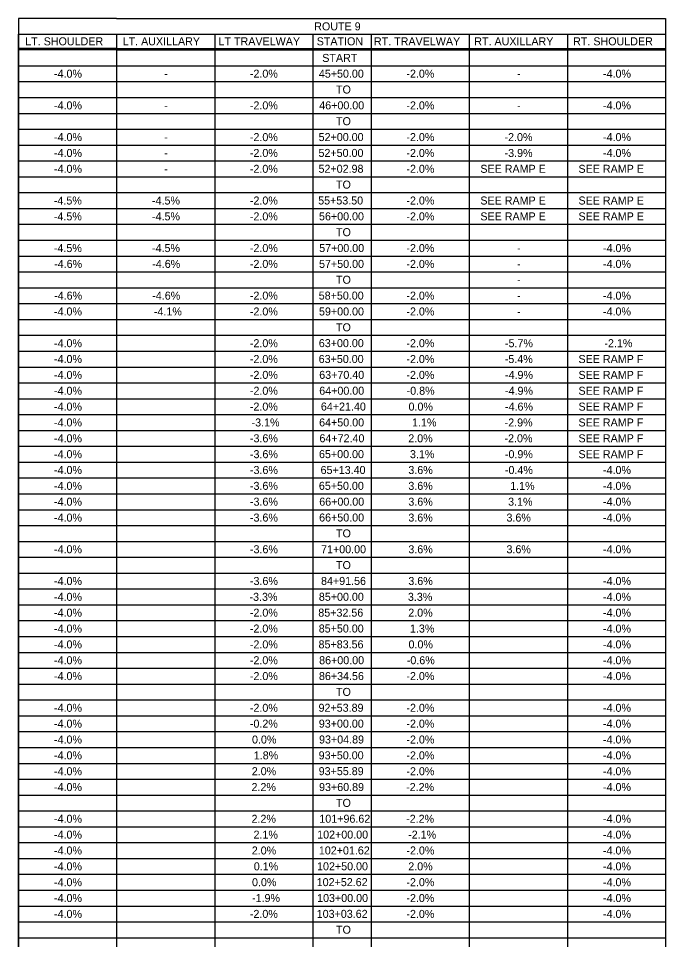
# Model space of a CAD drawing. Extents: x -15319374 to 1762012, y 465773 to 3693661.
# Drawn here: x -15318877.5 to -15318635, y 3691629.9 to 3691975.2 of the extents above; entities that cross this region are included whole.
import ezdxf

# ---------------------------------------------------------------- set-up
doc = ezdxf.new("R2010")
doc.units = 0
doc.layers.add('BORDER', color=7, linetype='Continuous')
doc.layers.add('DIMENSIONS', color=7, linetype='Continuous')

msp = doc.modelspace()

# ---------------------------------------------------------------- linework, layer by layer
at = {"layer": 'BORDER'}
for p, q in [((-15318877.49, 3691969.22), (-15318877.49, 3691464.16)), ((-15318840.73, 3691969.22), (-15318840.73, 3691285.88)), ((-15318803.96, 3691969.22), (-15318803.96, 3691285.88)), ((-15318767.19, 3691969.22), (-15318767.19, 3691285.88)), ((-15318745.32, 3691969.22), (-15318745.32, 3691285.88)), ((-15318708.55, 3691969.22), (-15318708.55, 3691285.88)), ((-15318671.78, 3691969.22), (-15318671.78, 3691285.88)), ((-15318635.01, 3691969.22), (-15318635.01, 3691464.16)), ((-15318840.73, 3691963.94), (-15318877.49, 3691963.94)), ((-15318840.73, 3691963.35), (-15318877.49, 3691963.35)), ((-15318877.49, 3691963.35), (-15318877.49, 3691285.88)), ((-15318840.73, 3691963.94), (-15318635.01, 3691963.94)), ((-15318840.73, 3691963.35), (-15318635.01, 3691963.35)), ((-15318877.49, 3691957.4), (-15318635.01, 3691957.4)), ((-15318877.49, 3691957.4), (-15318635.01, 3691957.4)), ((-15318877.49, 3691957.4), (-15318635.01, 3691957.4)), ((-15318877.49, 3691951.46), (-15318635.01, 3691951.46)), ((-15318877.49, 3691945.52), (-15318635.01, 3691945.52)), ((-15318877.49, 3691939.58), (-15318635.01, 3691939.58)), ((-15318877.49, 3691933.63), (-15318635.01, 3691933.63)), ((-15318877.49, 3691927.69), (-15318635.01, 3691927.69)), ((-15318877.49, 3691921.75), (-15318635.01, 3691921.75)), ((-15318877.49, 3691915.8), (-15318635.01, 3691915.8)), ((-15318877.49, 3691909.86), (-15318635.01, 3691909.86)), ((-15318877.49, 3691903.92), (-15318635.01, 3691903.92)), ((-15318877.49, 3691897.98), (-15318635.01, 3691897.98)), ((-15318877.49, 3691892.03), (-15318635.01, 3691892.03)), ((-15318877.49, 3691886.09), (-15318635.01, 3691886.09)), ((-15318877.49, 3691880.15), (-15318635.01, 3691880.15)), ((-15318877.49, 3691874.21), (-15318635.01, 3691874.21)), ((-15318877.49, 3691868.26), (-15318635.01, 3691868.26)), ((-15318877.49, 3691862.32), (-15318635.01, 3691862.32)), ((-15318877.49, 3691856.38), (-15318635.01, 3691856.38)), ((-15318877.49, 3691850.43), (-15318635.01, 3691850.43)), ((-15318877.49, 3691844.49), (-15318635.01, 3691844.49)), ((-15318877.49, 3691838.55), (-15318635.01, 3691838.55)), ((-15318877.49, 3691832.61), (-15318635.01, 3691832.61)), ((-15318877.49, 3691826.66), (-15318635.01, 3691826.66)), ((-15318877.49, 3691820.72), (-15318635.01, 3691820.72)), ((-15318877.49, 3691814.78), (-15318635.01, 3691814.78)), ((-15318877.49, 3691808.84), (-15318635.01, 3691808.84)), ((-15318877.49, 3691802.89), (-15318635.01, 3691802.89)), ((-15318877.49, 3691796.95), (-15318635.01, 3691796.95)), ((-15318877.49, 3691791.01), (-15318635.01, 3691791.01)), ((-15318877.49, 3691785.07), (-15318635.01, 3691785.07)), ((-15318877.49, 3691779.12), (-15318635.01, 3691779.12)), ((-15318877.49, 3691773.18), (-15318635.01, 3691773.18)), ((-15318877.49, 3691767.24), (-15318635.01, 3691767.24)), ((-15318877.49, 3691761.29), (-15318635.01, 3691761.29)), ((-15318877.49, 3691755.35), (-15318635.01, 3691755.35)), ((-15318877.49, 3691749.41), (-15318635.01, 3691749.41)), ((-15318877.49, 3691743.47), (-15318635.01, 3691743.47)), ((-15318877.49, 3691737.52), (-15318635.01, 3691737.52)), ((-15318877.49, 3691731.58), (-15318635.01, 3691731.58)), ((-15318877.49, 3691725.64), (-15318635.01, 3691725.64)), ((-15318877.49, 3691719.7), (-15318635.01, 3691719.7)), ((-15318877.49, 3691713.75), (-15318635.01, 3691713.75)), ((-15318877.49, 3691707.81), (-15318635.01, 3691707.81)), ((-15318877.49, 3691701.87), (-15318635.01, 3691701.87)), ((-15318877.49, 3691695.92), (-15318635.01, 3691695.92)), ((-15318877.49, 3691689.98), (-15318635.01, 3691689.98)), ((-15318877.49, 3691684.04), (-15318635.01, 3691684.04)), ((-15318877.49, 3691678.1), (-15318635.01, 3691678.1)), ((-15318877.49, 3691672.15), (-15318635.01, 3691672.15)), ((-15318877.49, 3691666.21), (-15318635.01, 3691666.21)), ((-15318877.49, 3691660.27), (-15318635.01, 3691660.27)), ((-15318877.49, 3691654.33), (-15318635.01, 3691654.33)), ((-15318877.49, 3691648.38), (-15318635.01, 3691648.38)), ((-15318877.49, 3691642.44), (-15318635.01, 3691642.44)), ((-15318877.49, 3691636.5), (-15318635.01, 3691636.5)), ((-15318877.49, 3691630.55), (-15318635.01, 3691630.55))]:
    msp.add_line(p, q, dxfattribs=at)
for points in [[(-15318840.73, 3691975.17), (-15318877.49, 3691975.17), (-15318877.49, 3691969.22)], [(-15318840.73, 3691975.17), (-15318671.78, 3691975.17)], [(-15318671.78, 3691975.17), (-15318635.01, 3691975.17), (-15318635.01, 3691969.22)]]:
    msp.add_lwpolyline(points, dxfattribs=at)
msp.add_lwpolyline([(-15318877.49, 3691969.22), (-15318635.01, 3691969.22), (-15318635.01, 3691624.61), (-15318877.49, 3691624.61)], close=True, dxfattribs=at)

# ---------------------------------------------------------------- texts
at = {"layer": 'DIMENSIONS'}
for s, p in [('ROUTE 9', (-15318766.66, 3691970.69)), ('LT. SHOULDER', (-15318874.94, 3691965.08)), ('LT. AUXILLARY', (-15318838.44, 3691965.08)), ('LT TRAVELWAY', (-15318802.51, 3691965.08)), ('STATION', (-15318765.73, 3691965.08)), ('RT. TRAVELWAY', (-15318744.29, 3691965.08)), ('RT. AUXILLARY', (-15318706.69, 3691965.08)), ('RT. SHOULDER', (-15318669.65, 3691965.08)), ('START', (-15318763.65, 3691958.86)), ('-4.0%', (-15318864.16, 3691952.95)), ('-', (-15318822.85, 3691952.95)), ('-2.0%', (-15318790.77, 3691952.95)), ('45+50.00', (-15318764.92, 3691952.96)), ('-2.0%', (-15318732.12, 3691952.95)), ('-', (-15318690.67, 3691952.95)), ('-4.0%', (-15318658.45, 3691952.95)), ('TO', (-15318758.49, 3691947.02)), ('-4.0%', (-15318864.16, 3691941.06)), ('-2.0%', (-15318790.77, 3691941.06)), ('46+00.00', (-15318764.78, 3691941.08)), ('-2.0%', (-15318732.12, 3691941.06)), ('-4.0%', (-15318658.45, 3691941.06)), ('-', (-15318822.85, 3691941.06)), ('-', (-15318690.67, 3691941.06)), ('TO', (-15318758.49, 3691935.14)), ('-4.0%', (-15318864.16, 3691929.18)), ('-2.0%', (-15318790.77, 3691929.18)), ('52+00.00', (-15318765.01, 3691929.19)), ('-2.0%', (-15318732.12, 3691929.18)), ('-2.0%', (-15318695.36, 3691929.18)), ('-4.0%', (-15318658.45, 3691929.18)), ('-', (-15318822.85, 3691929.18)), ('-4.0%', (-15318864.16, 3691923.23)), ('-2.0%', (-15318790.77, 3691923.23)), ('52+50.00', (-15318765.06, 3691923.25)), ('-2.0%', (-15318732.12, 3691923.23)), ('-3.9%', (-15318695.33, 3691923.23)), ('-4.0%', (-15318658.45, 3691923.23)), ('-', (-15318822.85, 3691923.23)), ('-4.0%', (-15318864.16, 3691917.29)), ('-', (-15318822.85, 3691917.29)), ('-2.0%', (-15318790.77, 3691917.29)), ('52+02.98', (-15318765.05, 3691917.31)), ('-2.0%', (-15318732.12, 3691917.29)), ('SEE RAMP E', (-15318704.41, 3691917.29)), ('SEE RAMP E', (-15318667.64, 3691917.29)), ('TO', (-15318758.49, 3691911.37)), ('-4.5%', (-15318864.21, 3691905.41)), ('-4.5%', (-15318827.44, 3691905.41)), ('-2.0%', (-15318790.77, 3691905.41)), ('55+53.50', (-15318765.18, 3691905.42)), ('-2.0%', (-15318732.12, 3691905.41)), ('SEE RAMP E', (-15318704.41, 3691905.41)), ('SEE RAMP E', (-15318667.64, 3691905.41)), ('-4.5%', (-15318864.21, 3691899.46)), ('-4.5%', (-15318827.44, 3691899.46)), ('-2.0%', (-15318790.77, 3691899.46)), ('56+00.00', (-15318764.87, 3691899.48)), ('-2.0%', (-15318732.12, 3691899.46)), ('SEE RAMP E', (-15318704.41, 3691899.46)), ('SEE RAMP E', (-15318667.64, 3691899.46)), ('TO', (-15318758.49, 3691893.54)), ('-4.5%', (-15318864.21, 3691887.58)), ('-4.5%', (-15318827.44, 3691887.58)), ('-2.0%', (-15318790.77, 3691887.58)), ('57+00.00', (-15318764.8, 3691887.59)), ('-2.0%', (-15318732.12, 3691887.58)), ('-', (-15318690.67, 3691887.58)), ('-4.0%', (-15318658.45, 3691887.58)), ('-4.6%', (-15318864.11, 3691881.64)), ('-4.6%', (-15318827.35, 3691881.64)), ('-2.0%', (-15318790.77, 3691881.64)), ('57+50.00', (-15318764.85, 3691881.65)), ('-2.0%', (-15318732.12, 3691881.64)), ('-4.0%', (-15318658.45, 3691881.64)), ('-', (-15318690.67, 3691881.64)), ('TO', (-15318758.49, 3691875.71)), ('-', (-15318690.67, 3691875.69)), ('-4.6%', (-15318864.11, 3691869.75)), ('-4.6%', (-15318827.35, 3691869.75)), ('-2.0%', (-15318790.77, 3691869.75)), ('58+50.00', (-15318764.97, 3691869.77)), ('-2.0%', (-15318732.12, 3691869.75)), ('-', (-15318690.67, 3691869.75)), ('-4.0%', (-15318658.45, 3691869.75)), ('-4.0%', (-15318864.16, 3691863.81)), ('-4.1%', (-15318826.73, 3691863.81)), ('-2.0%', (-15318790.77, 3691863.81)), ('59+00.00', (-15318764.87, 3691863.82)), ('-2.0%', (-15318732.12, 3691863.81)), ('-4.0%', (-15318658.45, 3691863.81)), ('-', (-15318690.67, 3691863.81)), ('TO', (-15318758.49, 3691857.88)), ('-4.0%', (-15318864.16, 3691851.92)), ('-2.0%', (-15318790.77, 3691851.92)), ('63+00.00', (-15318764.94, 3691851.94)), ('-2.0%', (-15318732.12, 3691851.92)), ('-5.7%', (-15318695.19, 3691851.92)), ('-2.1%', (-15318657.93, 3691851.92)), ('-4.0%', (-15318864.16, 3691845.98)), ('-2.0%', (-15318790.77, 3691845.98)), ('63+50.00', (-15318764.99, 3691846)), ('-2.0%', (-15318732.12, 3691845.98)), ('-5.4%', (-15318695.26, 3691845.98)), ('SEE RAMP F', (-15318667.64, 3691845.98)), ('-4.0%', (-15318864.16, 3691840.04)), ('-2.0%', (-15318790.77, 3691840.04)), ('63+70.40', (-15318764.78, 3691840.05)), ('-2.0%', (-15318732.12, 3691840.04)), ('-4.9%', (-15318695.17, 3691840.04)), ('SEE RAMP F', (-15318667.64, 3691840.04)), ('-4.0%', (-15318864.16, 3691834.09)), ('-2.0%', (-15318790.77, 3691834.09)), ('64+00.00', (-15318764.78, 3691834.11)), ('-0.8%', (-15318732.03, 3691834.09)), ('-4.9%', (-15318695.17, 3691834.09)), ('SEE RAMP F', (-15318667.64, 3691834.09)), ('-4.0%', (-15318864.16, 3691828.15)), ('-2.0%', (-15318790.77, 3691828.15)), ('64+21.40', (-15318764.16, 3691828.17)), ('0.0%', (-15318731.32, 3691828.15)), ('-4.6%', (-15318695.17, 3691828.15)), ('SEE RAMP F', (-15318667.64, 3691828.15)), ('-4.0%', (-15318864.16, 3691822.21)), ('-3.1%', (-15318790.13, 3691822.21)), ('64+50.00', (-15318764.82, 3691822.22)), ('1.1%', (-15318730, 3691822.21)), ('-2.9%', (-15318695.31, 3691822.21)), ('SEE RAMP F', (-15318667.64, 3691822.21)), ('-4.0%', (-15318864.16, 3691816.27)), ('-3.6%', (-15318790.74, 3691816.27)), ('64+72.40', (-15318764.7, 3691816.28)), ('2.0%', (-15318731.42, 3691816.27)), ('-2.0%', (-15318695.36, 3691816.27)), ('SEE RAMP F', (-15318667.64, 3691816.27)), ('-4.0%', (-15318864.16, 3691810.32)), ('-3.6%', (-15318790.74, 3691810.32)), ('65+00.00', (-15318764.87, 3691810.34)), ('3.1%', (-15318730.78, 3691810.32)), ('-0.9%', (-15318695.21, 3691810.32)), ('SEE RAMP F', (-15318667.64, 3691810.32)), ('-4.0%', (-15318864.16, 3691804.38)), ('-3.6%', (-15318790.74, 3691804.38)), ('65+13.40', (-15318764.28, 3691804.4)), ('3.6%', (-15318731.39, 3691804.38)), ('-0.4%', (-15318695.21, 3691804.38)), ('-4.0%', (-15318658.45, 3691804.38)), ('-4.0%', (-15318864.16, 3691798.44)), ('-3.6%', (-15318790.74, 3691798.44)), ('65+50.00', (-15318764.92, 3691798.45)), ('3.6%', (-15318731.39, 3691798.44)), ('1.1%', (-15318693.23, 3691798.44)), ('-4.0%', (-15318658.45, 3691798.44)), ('-4.0%', (-15318864.16, 3691792.5)), ('-3.6%', (-15318790.74, 3691792.5)), ('66+00.00', (-15318764.78, 3691792.51)), ('3.6%', (-15318731.39, 3691792.5)), ('3.1%', (-15318694.01, 3691792.5)), ('-4.0%', (-15318658.45, 3691792.5)), ('-4.0%', (-15318864.16, 3691786.55)), ('-3.6%', (-15318790.74, 3691786.55)), ('66+50.00', (-15318764.82, 3691786.57)), ('3.6%', (-15318731.39, 3691786.55)), ('3.6%', (-15318694.62, 3691786.55)), ('-4.0%', (-15318658.45, 3691786.55)), ('TO', (-15318758.49, 3691780.63)), ('-4.0%', (-15318864.16, 3691774.67)), ('-3.6%', (-15318790.74, 3691774.67)), ('71+00.00', (-15318764.09, 3691774.68)), ('3.6%', (-15318731.39, 3691774.67)), ('3.6%', (-15318694.62, 3691774.67)), ('-4.0%', (-15318658.45, 3691774.67)), ('TO', (-15318758.49, 3691768.74)), ('-4.0%', (-15318864.16, 3691762.78)), ('-3.6%', (-15318790.74, 3691762.78)), ('84+91.56', (-15318764.11, 3691762.8)), ('3.6%', (-15318731.39, 3691762.78)), ('-4.0%', (-15318658.45, 3691762.78)), ('-4.0%', (-15318864.16, 3691756.84)), ('-3.3%', (-15318790.91, 3691756.84)), ('85+00.00', (-15318764.92, 3691756.86)), ('3.3%', (-15318731.56, 3691756.84)), ('-4.0%', (-15318658.45, 3691756.84)), ('-4.0%', (-15318864.16, 3691750.9)), ('-2.0%', (-15318790.77, 3691750.9)), ('85+32.56', (-15318765.13, 3691750.91)), ('2.0%', (-15318731.42, 3691750.9)), ('-4.0%', (-15318658.45, 3691750.9)), ('-4.0%', (-15318864.16, 3691744.95)), ('-2.0%', (-15318790.77, 3691744.95)), ('85+50.00', (-15318764.97, 3691744.97)), ('1.3%', (-15318730.78, 3691744.95)), ('-4.0%', (-15318658.45, 3691744.95)), ('-4.0%', (-15318864.16, 3691739.01)), ('-2.0%', (-15318790.77, 3691739.01)), ('85+83.56', (-15318765.04, 3691739.03)), ('0.0%', (-15318731.32, 3691739.01)), ('-4.0%', (-15318658.45, 3691739.01)), ('-4.0%', (-15318864.16, 3691733.07)), ('-2.0%', (-15318790.77, 3691733.07)), ('86+00.00', (-15318764.82, 3691733.08)), ('-0.6%', (-15318731.98, 3691733.07)), ('-4.0%', (-15318658.45, 3691733.07)), ('-4.0%', (-15318864.16, 3691727.13)), ('-2.0%', (-15318790.77, 3691727.13)), ('86+34.56', (-15318764.89, 3691727.14)), ('-2.0%', (-15318732.12, 3691727.13)), ('-4.0%', (-15318658.45, 3691727.13)), ('TO', (-15318758.49, 3691721.2)), ('-4.0%', (-15318864.16, 3691715.24)), ('-2.0%', (-15318790.77, 3691715.24)), ('92+53.89', (-15318765.04, 3691715.26)), ('-2.0%', (-15318732.12, 3691715.24)), ('-4.0%', (-15318658.45, 3691715.24)), ('-4.0%', (-15318864.16, 3691709.3)), ('-0.2%', (-15318790.77, 3691709.3)), ('93+00.00', (-15318764.94, 3691709.31)), ('-2.0%', (-15318732.12, 3691709.3)), ('-4.0%', (-15318658.45, 3691709.3)), ('-4.0%', (-15318864.16, 3691703.35)), ('0.0%', (-15318789.97, 3691703.35)), ('93+04.89', (-15318764.85, 3691703.37)), ('-2.0%', (-15318732.12, 3691703.35)), ('-4.0%', (-15318658.45, 3691703.35)), ('-4.0%', (-15318864.16, 3691697.41)), ('1.8%', (-15318789.3, 3691697.41)), ('93+50.00', (-15318764.99, 3691697.43)), ('-2.0%', (-15318732.12, 3691697.41)), ('-4.0%', (-15318658.45, 3691697.41)), ('-4.0%', (-15318864.16, 3691691.47)), ('2.0%', (-15318790.06, 3691691.47)), ('93+55.89', (-15318764.99, 3691691.49)), ('-2.0%', (-15318732.12, 3691691.47)), ('-4.0%', (-15318658.45, 3691691.47)), ('-4.0%', (-15318864.16, 3691685.53)), ('2.2%', (-15318790.15, 3691685.53)), ('93+60.89', (-15318764.85, 3691685.54)), ('-2.2%', (-15318732.22, 3691685.53)), ('-4.0%', (-15318658.45, 3691685.53)), ('TO', (-15318758.49, 3691679.6)), ('-4.0%', (-15318864.16, 3691673.64)), ('2.2%', (-15318790.15, 3691673.64)), ('101+96.62', (-15318764.74, 3691673.66)), ('-2.2%', (-15318732.22, 3691673.64)), ('-4.0%', (-15318658.45, 3691673.64)), ('-4.0%', (-15318864.16, 3691667.7)), ('2.1%', (-15318789.4, 3691667.7)), ('102+00.00', (-15318765.55, 3691667.71)), ('-2.1%', (-15318731.46, 3691667.7)), ('-4.0%', (-15318658.45, 3691667.7)), ('-4.0%', (-15318864.16, 3691661.76)), ('2.0%', (-15318790.06, 3691661.76)), ('102+01.62', (-15318764.93, 3691661.77)), ('-2.0%', (-15318732.12, 3691661.76)), ('-4.0%', (-15318658.45, 3691661.76)), ('-4.0%', (-15318864.16, 3691655.81)), ('0.1%', (-15318789.3, 3691655.81)), ('102+50.00', (-15318765.6, 3691655.83)), ('2.0%', (-15318731.42, 3691655.81)), ('-4.0%', (-15318658.45, 3691655.81)), ('-4.0%', (-15318864.16, 3691649.87)), ('0.0%', (-15318789.97, 3691649.87)), ('102+52.62', (-15318765.73, 3691649.89)), ('-2.0%', (-15318732.12, 3691649.87)), ('-4.0%', (-15318658.45, 3691649.87)), ('-4.0%', (-15318864.16, 3691643.93)), ('-1.9%', (-15318789.96, 3691643.93)), ('103+00.00', (-15318765.58, 3691643.94)), ('-2.0%', (-15318732.12, 3691643.93)), ('-4.0%', (-15318658.45, 3691643.93)), ('-4.0%', (-15318864.16, 3691637.98)), ('-2.0%', (-15318790.77, 3691637.98)), ('103+03.62', (-15318765.73, 3691638)), ('-2.0%', (-15318732.12, 3691637.98)), ('-4.0%', (-15318658.45, 3691637.98)), ('TO', (-15318758.49, 3691632.06))]:
    msp.add_text(s, height=3, dxfattribs=at).set_placement(p)

doc.saveas('drawing.dxf')
